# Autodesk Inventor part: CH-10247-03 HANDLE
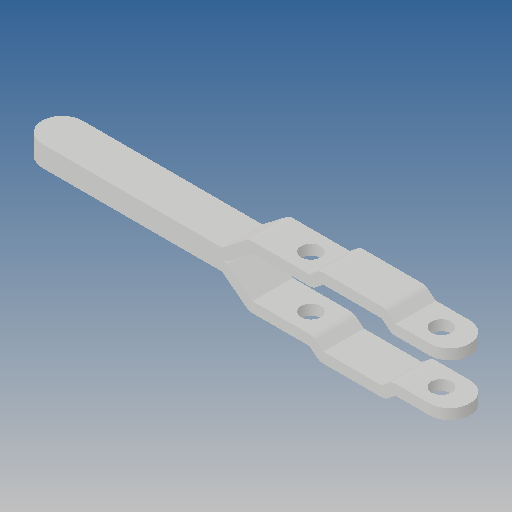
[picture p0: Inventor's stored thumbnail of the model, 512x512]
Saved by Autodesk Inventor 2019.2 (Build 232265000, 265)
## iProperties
Created: 2012-09
Part Number: CH-10247-03 HANDLE
Material: Ogólny
Document SubType Name: Modeling
Designer: CADENGINEERING4
Density: 1 g/cm^3
Appearance: Domyślna
Author: CADENGINEERING4
Revision Number: ÈÎºÎ
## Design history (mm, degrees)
feature "ÇÐ³ý-À­Éì1"
feature "¾µÏò1"
node "Bryła1"
node "Bryła2"
